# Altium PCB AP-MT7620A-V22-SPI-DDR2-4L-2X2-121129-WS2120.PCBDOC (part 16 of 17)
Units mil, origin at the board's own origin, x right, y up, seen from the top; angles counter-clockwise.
Board outline 7316 x 4279 mil, 4 copper layers (Top, Inner Layer 2, Inner Layer 3, Bottom), stack 35.4 mil thick; 640 components, 473 nets, 2041 pads, 2358 vias.
Unrouted connection lines stored in the file: 11.
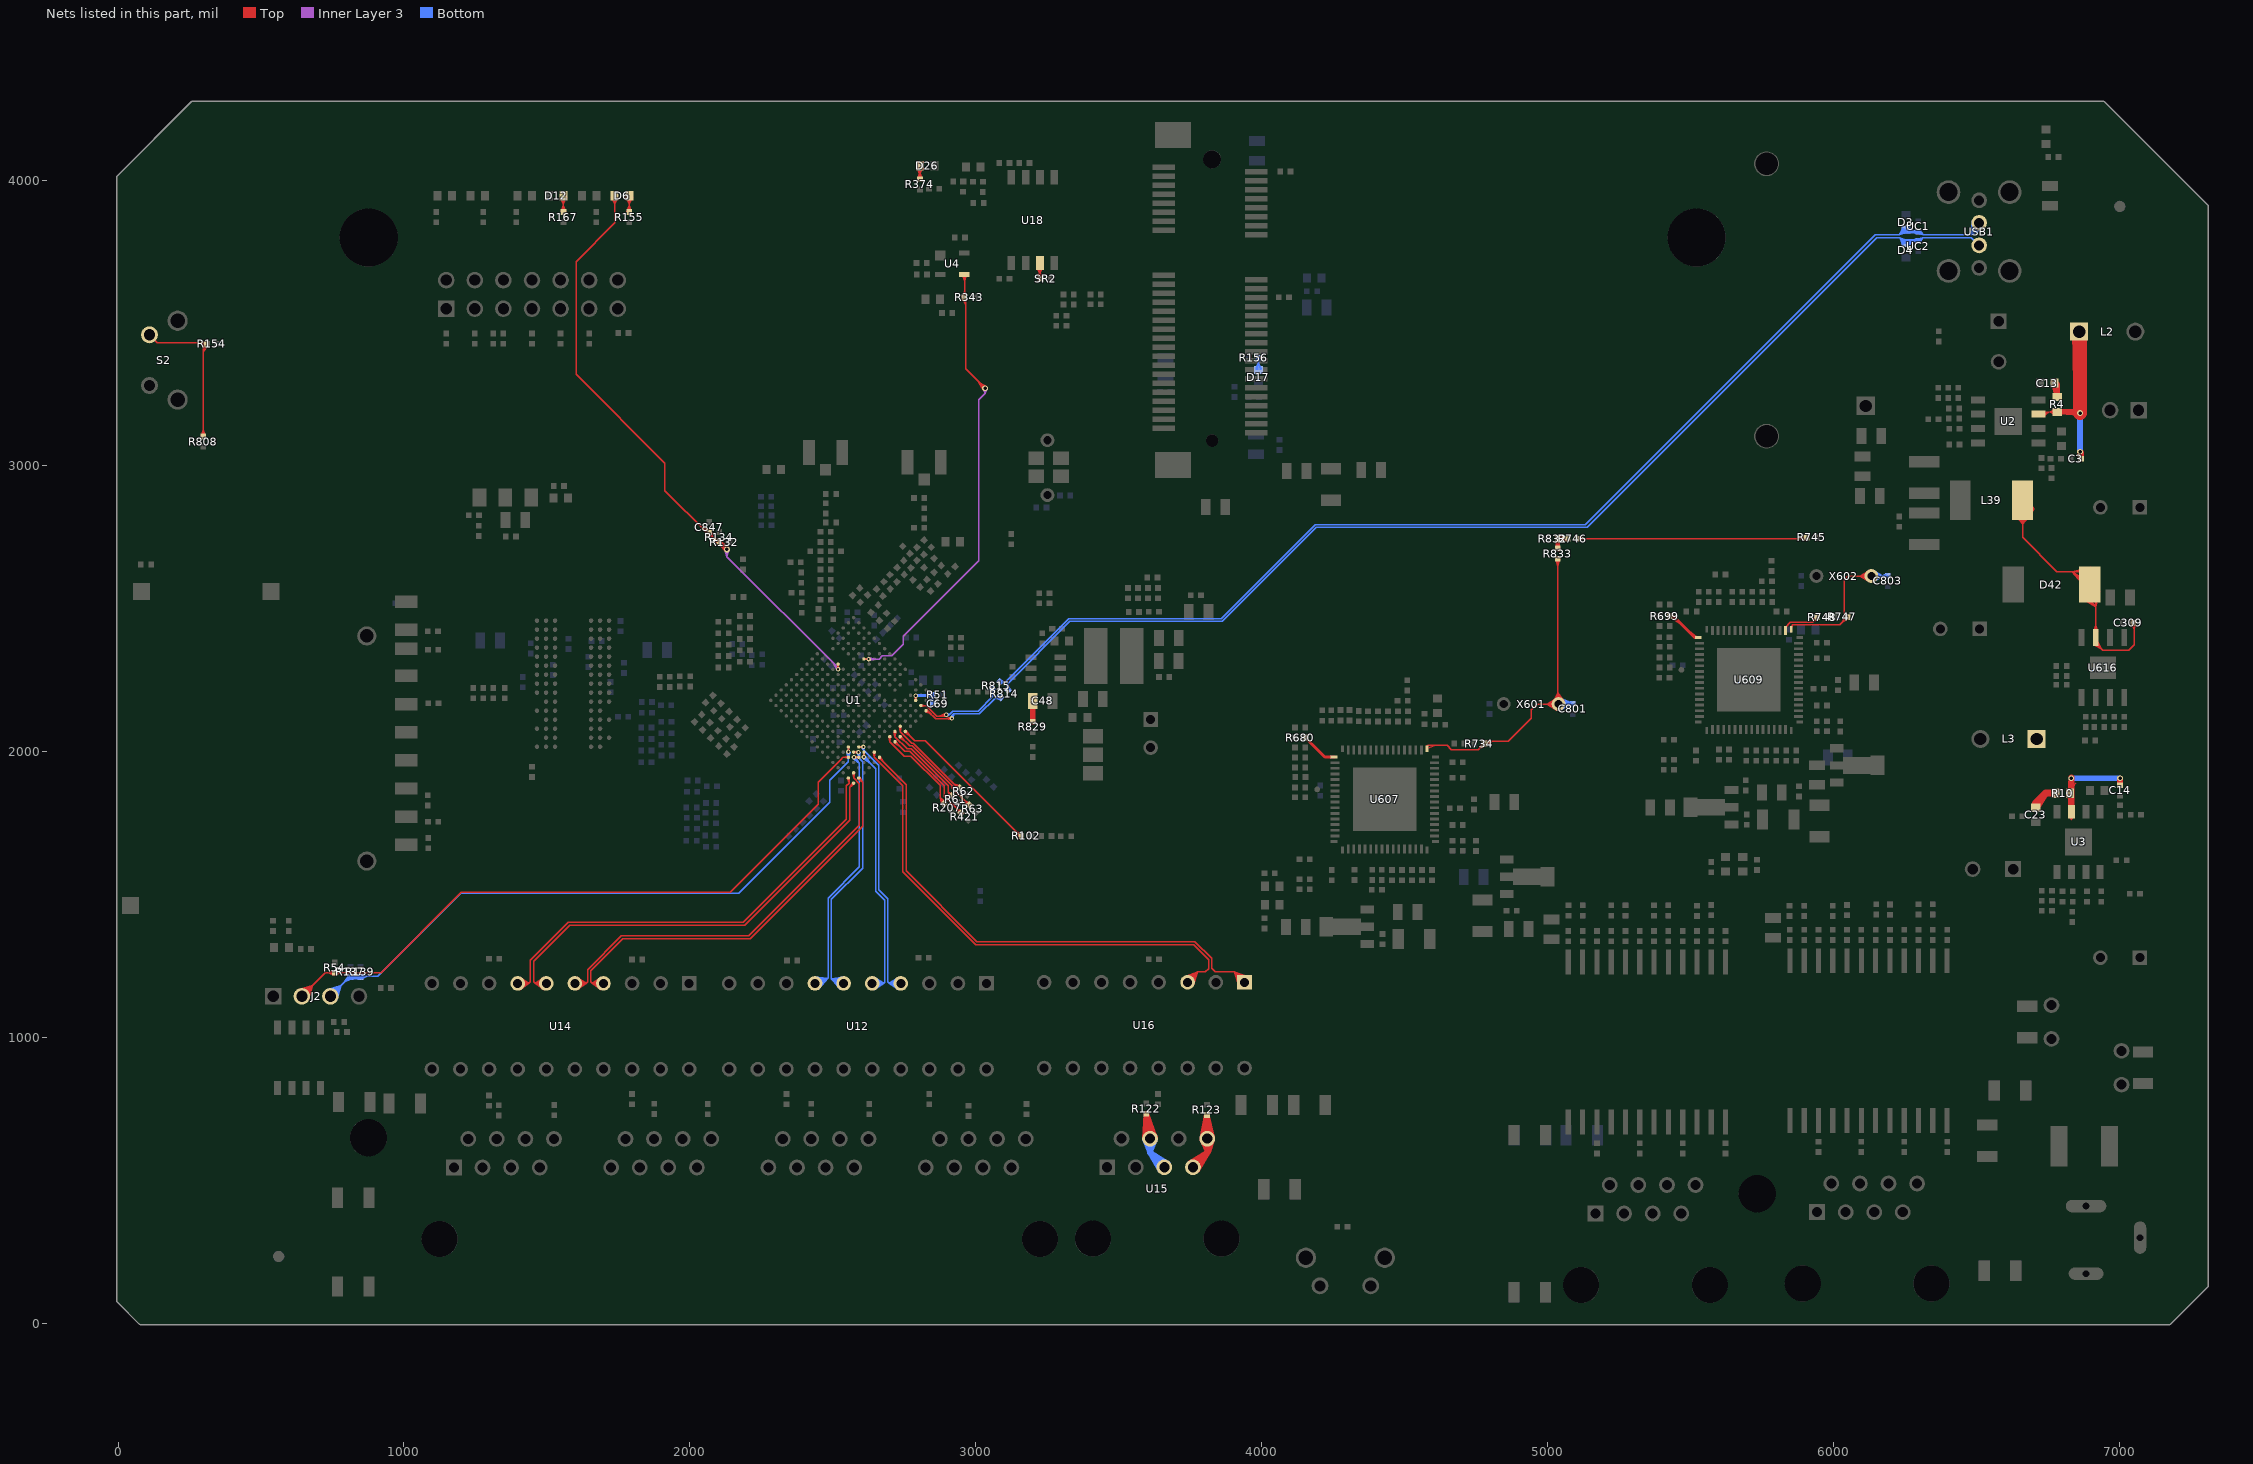
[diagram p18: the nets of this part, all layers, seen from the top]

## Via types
v1: diameter 20, hole 12, Top to Bottom, 2117 vias
v2: diameter 16, hole 8, Top to Bottom, 241 vias

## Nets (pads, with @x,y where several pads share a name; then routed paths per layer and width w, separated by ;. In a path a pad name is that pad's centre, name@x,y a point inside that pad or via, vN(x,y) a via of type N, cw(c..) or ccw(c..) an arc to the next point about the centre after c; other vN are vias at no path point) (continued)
SW1_5-POWER0: C14.2 L3.1 R10.1 U3.3 | length 1273.6
  Top w4: R10.1@6819.19,1864.46 6843.69,1885.69 ; R10.1@6822.03,1861.57 6843.69,1885.69 ; U3.3@6823.33,1775.25 6833,1762.5 ; R10.1@6825.17,1859.08 6843.69,1885.69 ; U3.3@6826.91,1777.3 6833,1762.5 ; R10.1@6828.59,1855 6828.59,1870.59 6850.5,1892.5 ; R10.1@6828.59,1857 6843.69,1885.69 ; U3.3@6830.8,1778.35 6833,1762.5 ; R10.1@6832.24,1855.36 6843.69,1885.69 ; U3.3@6833,1778.5 6833,1762.5 ; U3.3@6833,1789.33 6833,1762.5 ; U3.3@6835.2,1778.35 6833,1762.5 ; R10.1@6836.08,1854.18 6843.69,1885.69 ; U3.3@6839.09,1777.3 6833,1762.5 ; R10.1@6840.06,1853.47 6843.69,1885.69 ; U3.3@6842.67,1775.25 6833,1762.5
  Top w20: R10.1@6828.59,1855 6833,1850.59 6833,1829 ; 6833,1835.98 v1(6832,1908) ; R10.1@6828.59,1853 6833,1829 ; R10.1@6828.59,1853 6833,1829 ; R10.1@6828.59,1853 6833,1802.72 6833,1829 ; R10.1@6828.59,1853 6833,1829 ; R10.1@6828.59,1853 6833,1829 ; R10.1@6828.59,1853 6833,1789.33 6833,1829 ; v1(6832,1908) v1@6833,1911 ; v1(6832,1908) 6828.59,1857 v1@6833,1911 ; 6833,1829 v1@6833,1911 ; C14.2@7003,1883 v1(7003,1908) C14.2@7003,1883
  Bottom w20: v1(6832,1908) v1(7003,1908) 6931,1908
SW2_5-POWER0: C3.2 L2.1 R4.1 U2.3 | length 1467.3
  Top w4: U2.3@6717.61,3181 6717.61,3187.02 6720,3189.41 R4.1@6783,3189.41 ; U2.3@6728.39,3191.12 6754.55,3189.41 ; U2.3@6728.44,3187.07 6754.55,3189.41 ; U2.3@6729.1,3183.12 6754.55,3189.41 ; U2.3@6729.72,3181 6754.55,3189.41 ; U2.3@6730.51,3178.94 6754.55,3189.41 ; U2.3@6732.39,3175.4 6754.55,3189.41 ; U2.3@6734.81,3172.16 6754.55,3189.41 ; R4.1@6778.23,3177.73 6755,3189.41 ; R4.1@6778.23,3201.09 6755,3189.41 ; R4.1@6779.77,3181.5 6755,3189.41 ; R4.1@6779.77,3197.31 6755,3189.41 ; R4.1@6780.69,3185.42 6755,3189.41 ; R4.1@6780.69,3193.4 6755,3189.41 ; R4.1@6781,3189.41 6755,3189.41
  Top w4.5: R4.1@6782,3188.41 R4.1@6783,3189.41
  Top w20: R4.1@6783,3189.41 v1@6858.59,3189.41 ; R4.1@6785,3189.41 v1@6858.59,3189.41 ; v1@6858.59,3189.41 v1(6863,3185) ; v1(6863,3185) 6790.13,3189.41 v1(6863,3185) ; v1(6863,3050) 6866,3047 C3.2@6866,3025 v1(6863,3050)
  Top w50: v1(6863,3185) 6863,3466.57 L2.1@6859.57,3470 6863,3288.34
  Bottom w20: v1(6863,3050) v1(6863,3185) 6863,3113
SW11_5-POWER0: C309.2 D42.2 L39.1 U616.3 | length 3113.5
  Top w4: D42.2@6897.06,2585 D42.2@6897.06,2630
  Top w4.5: L39.1@6630.15,2835.83 6662.25,2797.6 ; L39.1@6633.92,2838.7 6662.25,2797.6 ; L39.1@6637.9,2841.17 6662.25,2797.6 ; L39.1@6642.03,2843.24 6662.25,2797.6 ; L39.1@6646.3,2844.9 6662.25,2797.6 ; L39.1@6662.25,2880 6662.25,2750 6782.25,2630 6897.06,2630 6917.06,2630 6917.06,2570 6918,2569.06 U616.3@6918,2399.33 6923,2394.33 6923,2375 6943,2355 7033,2355 7053,2375 7053,2448 C309.2@7049,2452 7053,2427.56 ; L39.1@6678.21,2844.9 6662.25,2797.6 ; L39.1@6682.47,2843.24 6662.25,2797.6 ; L39.1@6686.61,2841.17 6662.25,2797.6 ; L39.1@6690.58,2838.7 6662.25,2797.6 ; L39.1@6694.36,2835.83 6662.25,2797.6 ; D42.2@6869.64,2537.58 6918,2506.88 ; D42.2@6872.32,2541.44 6918,2506.88 ; D42.2@6875.27,2545.03 6918,2506.88 ; D42.2@6877.22,2580.31 6835.19,2630 ; D42.2@6878.47,2548.34 6918,2506.88 ; D42.2@6880.66,2583.44 6835.19,2630 ; D42.2@6881.9,2551.36 6918,2506.88 ; D42.2@6883.84,2586.78 6835.19,2630 ; D42.2@6886.76,2590.31 6835.19,2630 ; D42.2@6889.41,2594.01 6835.19,2630 ; D42.2@6898.44,2645.32 6835.19,2630 ; D42.2@6899.37,2640.76 6835.19,2630 ; D42.2@6899.97,2636.19 6835.19,2630 ; D42.2@6900.2,2627.06 6835.19,2630 ; D42.2@6900.25,2631.62 6835.19,2630 ; U616.3@6910.32,2420.11 6918,2442.36 ; U616.3@6913.31,2373.62 6938.38,2359.62 ; D42.2@6914.18,2564.04 6918,2506.88 ; U616.3@6914.72,2419.05 6918,2442.36 ; U616.3@6915.82,2377.38 6938.38,2359.62 ; U616.3@6918,2379.84 6938.38,2359.62 ; U616.3@6918,2418.82 6918,2442.36 ; D42.2@6918.74,2564.16 6918,2506.88 ; U616.3@6920.45,2382.04 6938.38,2359.62 ; U616.3@6921.28,2419.05 6918,2442.36 ; D42.2@6923.34,2563.91 6918,2506.88 ; U616.3@6924.19,2384.58 6938.38,2359.62 ; U616.3@6925.68,2420.11 6918,2442.36 ; D42.2@6927.95,2563.29 6918,2506.88 ; D42.2@6932.54,2562.29 6918,2506.88 ; C309.2@7041.64,2449.57 7053,2427.56 ; C309.2@7045.83,2451.27 7053,2427.56 ; C309.2@7052.24,2452.31 7053,2427.56 ; C309.2@7056.75,2452.04 7053,2427.56
  Top w20: L39.1@6662.25,2880 L39.1@6693,2849.25
SW_C2_5-POWER0: C13.1 R4.2 | length 104.2
  Top w20: C13.1@6773.59,3288 R4.2@6783,3240.59 6783,3285 6778.59,3285 C13.1@6773.59,3290
SW_C_5-POWER0: C23.1 R10.2 | length 209.2
  Top w25: C23.1@6710,1805.59 6742.5,1855.5 ; 6708,1821 6742.5,1855.5 ; 6708,1821 C23.1@6708,1805.59 6708,1821 ; 6742.5,1855.5 6776.91,1855.5 R10.2@6777.41,1855 6742.5,1855.5
TXCLK_1-CPU-RT0: R102.2 U1.G17 | length 709.6
  Top w5: U1.G17@2751.76,2068.82 2768.79,2056.71 ; U1.G17@2756.54,2073.64 2768.79,2056.71 ; R102.2@3153.41,1701 3136.71,1725.29 ; R102.2@3163.15,1712.25 3136.71,1725.29 ; 2768.79,2056.71 U1.G17@2753.95,2071.43 2754.07,2071.43 2786.5,2039 2823,2039 3152,1710 3156,1710 3160,1706 R102.2@3159,1706 3136.71,1725.29
TXD0_1-CPU-RT0: R63.2 U1.H17 | length 523
  Top w4.5: U1.H17@2733.53,2050.52 2749.58,2039.61 ; U1.H17@2738.67,2055.66 2749.58,2039.61 ; R63.2@2970.68,1809.94 2960.37,1831.06 ; R63.2@2974.54,1812.31 2960.37,1831.06 ; R63.2@2976.99,1814.45 2960.37,1831.06 ; R63.2@2977.7,1813.74 2978.4,1813.03 2918,1873.43 2918,1880.62 2778.04,2020.57 2768.62,2020.57 U1.H17@2735.86,2053.33 2749.58,2039.61 ; R63.2@2979.12,1816.9 2960.37,1831.06 ; R63.2@2981.49,1820.75 2960.37,1831.06
TXD1_1-CPU-RT0: R61.2 U1.H16 | length 463.6
  Top w4.5: U1.H16@2714.13,2071.06 2717.76,2053.34 ; U1.H16@2721.4,2071.06 2717.76,2053.34 ; R61.2@2910.36,1842.08 2904.08,1859.08 ; R61.2@2914.39,1844.18 2904.08,1859.08 ; R61.2@2916.89,1846.27 2904.08,1859.08 ; R61.2@2917.59,1845.56 2918.3,1844.85 2904.08,1859.08 ; R61.2@2918.97,1848.76 2904.08,1859.08 ; R61.2@2921.07,1852.79 2904.08,1859.08 ; 2717.76,2053.34 U1.H16@2717.76,2071.43 2717.76,2053.34 ; 2717.76,2053.34 2760.29,2010.81 2774.19,2010.81 2904.08,1880.92 2904.08,1859.08
TXD2_1-CPU-RT0: R421.2 U1.J17 | length 534.5
  Top w4.5: U1.J17@2715.48,2032.38 2731.74,2021.76 ; U1.J17@2720.54,2037.62 2731.74,2021.76 ; R421.2@2942.28,1781.83 2932.51,1803.24 ; R421.2@2946.2,1784.09 2932.51,1803.24 ; R421.2@2948.7,1786.16 2932.51,1803.24 ; R421.2@2949.41,1785.45 2950.12,1784.75 2945.75,1789.12 2945.75,1790 2890.75,1845 2890.75,1880.75 2770.25,2001.26 2752.24,2001.26 2718.26,2035.24 U1.J17@2717.76,2035.24 2731.74,2021.76 ; R421.2@2950.9,1788.56 2932.51,1803.24 ; R421.2@2953.37,1792.35 2932.51,1803.24
TXD3_1-CPU-RT0: R207.2 U1.J16 | length 514
  Top w4.5: U1.J16@2696.04,2052.88 2700.13,2034.87 ; U1.J16@2703.31,2053.06 2700.13,2034.87 ; R207.2@2881.41,1815.1 2875.86,1839.39 ; R207.2@2885.71,1816.5 2875.86,1839.39 ; R207.2@2888.6,1817.98 2875.86,1839.39 ; R207.2@2890.01,1816.57 2889.33,1817.25 2888,1817.25 2893,1822.25 2875.25,1840 2875.25,1882.8 2773.05,1985 2750,1985 2700.13,2034.87 ; R207.2@2891.28,1819.82 2875.86,1839.39 ; R207.2@2894.56,1822.93 2875.86,1839.39 ; 2700.13,2034.87 2700.13,2052.87 U1.J16@2699.67,2053.33 2700.13,2034.87
TXDELAY_IP1001-2_1-CPU-RT0: R699.1 U609.49 | length 235
  Top w10: 5465.42,2449.58 R699.1@5428,2475 ; 5493.63,2421.37 U609.49@5520.93,2399.69 ; U609.49@5527.82,2399.69 5527.51,2400 5515,2400 ; R699.1@5428,2475 5440,2475 ; R699.1@5428,2475 5440,2475 ; 5440,2475 5515,2400 ; 5515,2400 U609.49@5520.93,2399.69 ; 5515,2400 U609.49@5520.93,2399.69
TXDELAY_IP1001_1-CPU-RT0: R680.1 U607.49 | length 154.7
  Top w10: R680.1@4153,2050 4221.31,1981.69 ; U607.49@4246.93,1981.69 4221.31,1981.69 ; U607.49@4253.82,1981.69 4221.31,1981.69
TXEN_1-CPU-RT0: R62.2 U1.G16 | length 497.5
  Top w4.5: U1.G16@2732.23,2089.04 2736.53,2070.77 ; U1.G16@2739.51,2089.3 2736.53,2070.77 ; R62.2@2940.03,1868.75 2923.46,1888.6 ; R62.2@2943.24,1871.94 2923.46,1888.6 ; R62.2@2945.17,1874.55 2923.46,1888.6 ; R62.2@2945.88,1873.84 2946.58,1873.14 2938.93,1873.14 2781.87,2030.2 2777.1,2030.2 2736.53,2070.77 ; R62.2@2946.76,1877.38 2923.46,1888.6 ; R62.2@2948.36,1881.61 2923.46,1888.6 ; 2736.53,2070.77 2736.53,2088.85 U1.G16@2735.86,2089.52 2736.53,2070.77
TXOM0: U1.U17 U14.6 | length 1993.7
  Top w5: U14.6@1491.16,1167.94 1459,1190 ; U14.6@1491.16,1212.06 1459,1190 ; U14.6@1493.8,1172.4 1459,1190 ; U14.6@1493.8,1207.6 1459,1190 ; U14.6@1495.8,1177.1 1459,1190 ; U14.6@1495.8,1202.9 1459,1190 ; U14.6@1497.16,1181.95 1459,1190 ; U14.6@1497.16,1198.05 1459,1190 ; U14.6@1497.88,1186.91 1459,1190 ; U14.6@1497.88,1193.09 1459,1190 ; U14.6@1498,1190 1459,1190 ; U1.U17@2570.39,1892.67 2559,1876.48 ; U1.U17@2573,1890.48 2559,1876.48 ; U1.U17@2575.19,1887.87 2559,1876.48 ; 1459,1190 1453.5,1195.5 1453.5,1267.23 1579.27,1393 2191.56,1393 2559,1760.44 2559,1809.82 2559,1876.48
TXOM1: U1.T17 U14.4 | length 1870.1
  Top w5: U14.4@1691.16,1167.94 1659,1190 ; U14.4@1691.16,1212.06 1659,1190 ; U14.4@1693.8,1172.4 1659,1190 ; U14.4@1693.8,1207.6 1659,1190 ; U14.4@1695.8,1177.1 1659,1190 ; U14.4@1695.8,1202.9 1659,1190 ; U14.4@1697.16,1181.95 1659,1190 ; U14.4@1697.16,1198.05 1659,1190 ; U14.4@1697.88,1186.91 1659,1190 ; U14.4@1697.88,1193.09 1659,1190 ; U14.4@1698,1190 1659,1190 ; U1.T17@2588.8,1906.06 2604.5,1894 ; U1.T17@2593.79,1910.65 2604.5,1894 ; 1659,1190 1653.5,1195.5 1653.5,1233.83 1765.67,1346 2211.06,1346 2604.5,1739.44 2604.5,1894 ; 2604.5,1894 2590.51,1907.99 U1.T17@2591.1,1908.57 2604.5,1894
TXOM2: U1.P15 U12.7 | length 1479.8
  Top w5: U1.P15@2591.05,1981 U1.P15@2591.1,1980.95
  Top w8: U1.P15@2591.05,1981 v2(2574.5,1981) U1.P15@2591.1,1980.95
  Bottom w5: U12.7@2434.44,1207.74 2482.69,1208.19 ; U12.7@2434.67,1212.85 2482.69,1208.19 ; U12.7@2434.76,1202.68 2482.69,1208.19 ; U12.7@2435.59,1197.72 2482.69,1208.19 ; U12.7@2436.93,1192.9 2482.69,1208.19 ; U12.7@2438,1190 2464.5,1190 2483.5,1209 2483.5,1488.12 2593.5,1598.12 2593.5,1959.5 2577.5,1975.5 2577.5,1978 v2(2574.5,1981) 2593.32,1959.68 ; U12.7@2439.26,1187.18 2482.69,1208.19 ; U12.7@2441.67,1182.79 2482.69,1208.19 ; U12.7@2444.53,1178.66 2482.69,1208.19 ; U12.7@2447.84,1174.82 2482.69,1208.19 ; U12.7@2451.57,1171.32 2482.69,1208.19 ; v2@2570.75,1976.98 2593.32,1959.68 ; v2@2578.96,1984.22 2593.32,1959.68
TXOM3: U1.N14 U12.4 | length 1402.4
  Top w8: U1.N14@2591.1,2017.14 2607.44,2017.14 U1.N14@2591.1,2017.14 ; U1.N14@2591.1,2017.14 v2(2607.5,2017.2) U1.N14@2591.1,2017.14
  Top w10: v2@2607.44,2017.14 v2(2607.5,2017.2)
  Bottom w5: v2@2602.18,2015.79 2607.5,2006.5 ; v2@2612.82,2015.79 2607.5,2006.5 ; U12.4@2731.34,1167.89 2698,1190 ; U12.4@2731.34,1212.11 2698,1190 ; U12.4@2733.91,1172.38 2698,1190 ; U12.4@2733.91,1207.62 2698,1190 ; U12.4@2735.86,1177.09 2698,1190 ; U12.4@2735.86,1202.91 2698,1190 ; U12.4@2737.18,1181.95 2698,1190 ; U12.4@2737.18,1198.05 2698,1190 ; U12.4@2737.88,1186.91 2698,1190 ; U12.4@2737.88,1193.09 2698,1190 ; U12.4@2738,1190 2698,1190 ; 2607.5,2006.5 v2(2607.5,2017.2) 2607.5,2006.5 ; 2607.5,2006.5 2661,1953 2661,1517 2692.5,1485.5 2692.5,1195.5 2698,1190
TXOM4: U1.M17 U16.1 | length 2374.1
  Top w5: U1.M17@2661.07,1978.55 2677.26,1964.74 ; U1.M17@2666.24,1982.94 2677.26,1964.74 ; U16.1@3920.79,1181.8 3904.39,1230 ; U16.1@3925.53,1183.68 3904.39,1230 ; U16.1@3930.02,1186.01 3904.39,1230 ; U16.1@3934.24,1188.75 3904.39,1230 ; U16.1@3938.14,1191.88 3904.39,1230 ; U16.1@3940.39,1194 3904.39,1230 ; U16.1@3942.51,1196.25 3904.39,1230 ; U16.1@3945.64,1200.16 3904.39,1230 ; U16.1@3948.38,1204.37 3904.39,1230 ; U16.1@3950.71,1208.86 3904.39,1230 ; U16.1@3952.59,1213.6 3904.39,1230 ; 2677.26,1964.74 U1.M17@2663.48,1980.95 2663.48,1978.52 2756.5,1885.5 2756.5,1584.28 3004.28,1336.5 3766.72,1336.5 3825.5,1277.72 3825.5,1243 3838.5,1230 3904.39,1230
TXOP0: U1.U16 U14.7 | length 2026.4
  Top w5: U14.7@1398,1190 1437,1190 ; U14.7@1398.12,1186.91 1437,1190 ; U14.7@1398.12,1193.09 1437,1190 ; U14.7@1398.84,1181.95 1437,1190 ; U14.7@1398.84,1198.05 1437,1190 ; U14.7@1400.2,1177.1 1437,1190 ; U14.7@1400.2,1202.9 1437,1190 ; U14.7@1402.2,1172.4 1437,1190 ; U14.7@1402.2,1207.6 1437,1190 ; U14.7@1404.84,1167.94 1437,1190 ; U14.7@1404.84,1212.06 1437,1190 ; U1.U16@2551.58,1907.84 2557.2,1890.3 ; U1.U16@2558.31,1908.68 2557.2,1890.3 ; 1437,1190 1442.5,1195.5 1442.5,1271.79 1574.71,1404 2187,1404 2548,1765 2548,1881.1 2557.2,1890.3 ; 2557.2,1890.3 2557.2,1906.28 U1.U16@2554.9,1908.57 2557.2,1890.3
TXOP1: U1.T16 U14.5 | length 1885.5
  Top w5: U14.5@1598,1190 1637,1190 ; U14.5@1598.12,1186.91 1637,1190 ; U14.5@1598.12,1193.09 1637,1190 ; U14.5@1598.84,1181.95 1637,1190 ; U14.5@1598.84,1198.05 1637,1190 ; U14.5@1600.2,1177.1 1637,1190 ; U14.5@1600.2,1202.9 1637,1190 ; U14.5@1602.2,1172.4 1637,1190 ; U14.5@1602.2,1207.6 1637,1190 ; U14.5@1604.84,1167.94 1637,1190 ; U14.5@1604.84,1212.06 1637,1190 ; U1.T16@2569.61,1926.35 2573,1908.6 ; U1.T16@2576.39,1926.35 2573,1908.6 ; 1637,1190 1642.5,1195.5 1642.5,1238.39 1761.11,1357 2206.5,1357 2593.5,1744 2593.5,1888.1 2573,1908.6 ; 2573,1908.6 U1.T16@2573,1926.67 2573,1908.6
TXOP2: U1.P14 U12.6 | length 2035.5
  Top w8: U1.P14@2573,1999.05 v2(2590,1999) U1.P14@2573,1999.05 ; U1.P14@2573,1999.05 v2(2590,1999) U1.P14@2573,1999.05
  Top w10: v2(2590,1999) v2(2590,1999)
  Bottom w5: U12.6@2524.68,1171.14 2495.87,1205.63 ; U12.6@2528.42,1174.65 2495.87,1205.63 ; U12.6@2531.71,1178.52 2495.87,1205.63 ; U12.6@2534.51,1182.7 2495.87,1205.63 ; U12.6@2536.83,1187.14 2495.87,1205.63 ; U12.6@2538,1190 2533,1190 2531.5,1191.5 2510,1191.5 ; U12.6@2538.97,1192.93 2495.87,1205.63 ; U12.6@2540.12,1197.81 2495.87,1205.63 ; U12.6@2540.2,1212.99 2495.87,1205.63 ; U12.6@2540.72,1202.81 2495.87,1205.63 ; U12.6@2540.75,1207.88 2495.87,1205.63 ; v2@2584.64,1997.77 2592,1978 ; v2@2595.5,1998.8 2592,1978 ; 2510,1191.5 2494.5,1207 2494.5,1483.56 2604.5,1593.56 2604.5,1965.5 2592,1978 ; 2510,1191.5 2527.38,1169.5 2510,1191.5 ; 2510,1191.5 2529.63,1211.52 2510,1191.5 ; 2510,1191.5 2531.26,1173.21 2510,1191.5 ; 2510,1191.5 2533.09,1207.41 2510,1191.5 ; 2510,1191.5 2534.27,1177.45 2510,1191.5 ; 2510,1191.5 2535.63,1202.87 2510,1191.5 ; 2510,1191.5 2536.41,1182.07 2510,1191.5 ; 2510,1191.5 2537.26,1198.06 2510,1191.5 ; 2510,1191.5 2537.66,1186.93 2510,1191.5 ; 2510,1191.5 2538,1193.09 2510,1191.5 ; 2592,1978 2592,1997 v2(2590,1999) 2592,1978
TXOP3: U1.N15 U12.5 | length 1390.2
  Top w8: U1.N15@2609.19,1999.05 2609.19,1981.99 U1.N15@2609.19,1999.05 ; U1.N15@2609.19,1999.05 v2(2609.1,1981.9) U1.N15@2609.19,1999.05
  Top w10: v2(2609.1,1981.9) v2@2609.19,1981.99
  Bottom w5: v2@2605.6,1977.66 2629.72,1961.33 v2@2613.33,1985.41 ; v2(2609.1,1981.9) 2650,1941.1 2650,1512.5 2650,1512.44 2681.5,1480.94 2681.5,1193.5 2678,1190 ; U12.5@2638,1190 2678,1190 ; U12.5@2638.12,1186.91 2678,1190 ; U12.5@2638.12,1193.09 2678,1190 ; U12.5@2638.82,1181.95 2678,1190 ; U12.5@2638.82,1198.05 2678,1190 ; U12.5@2640.14,1177.09 2678,1190 ; U12.5@2640.14,1202.91 2678,1190 ; U12.5@2642.09,1172.38 2678,1190 ; U12.5@2642.09,1207.62 2678,1190 ; U12.5@2644.66,1167.89 2678,1190 ; U12.5@2644.66,1212.11 2678,1190
TXOP4: U1.M16 U16.3 | length 2344.6
  Top w4.5: U1.M16@2641.74,1998.68 2645.38,1981 ; U1.M16@2649.02,1998.68 2645.38,1981 ; 2668,1958.38 2645.38,1981 ; 2645.38,1981 U1.M16@2645.38,1999.05 2645.38,1981
  Top w5: 2668,1958.38 2745.5,1880.88 2745.5,1579.72 2999.72,1325.5 3762.16,1325.5 3814.5,1273.16 3814.5,1241.5 3803,1230 3777.3,1230 ; U16.3@3729.1,1213.6 3777.3,1230 ; U16.3@3730.98,1208.86 3777.3,1230 ; U16.3@3733.31,1204.37 3777.3,1230 ; U16.3@3736.05,1200.16 3777.3,1230 ; U16.3@3739.18,1196.25 3777.3,1230 ; U16.3@3741.3,1194 3777.3,1230 ; U16.3@3743.55,1191.88 3777.3,1230 ; U16.3@3747.46,1188.75 3777.3,1230 ; U16.3@3751.67,1186.01 3777.3,1230 ; U16.3@3756.16,1183.68 3777.3,1230 ; U16.3@3760.9,1181.8 3777.3,1230
UART_RX_1-CPU-RT0: J2.2 R54.1 U1.R14 | length 3226.2
  Top w4.5: J2.2@629.3,1167.98 681.55,1183.55 ; J2.2@630.81,1163.61 681.55,1183.55 ; J2.2@632.66,1159.43 681.55,1183.55 ; J2.2@634.84,1155.44 681.55,1183.55 ; J2.2@637.33,1151.66 681.55,1183.55 ; J2.2@643,1145 725,1227 ; J2.2@649.66,1139.33 681.55,1183.55 ; J2.2@653.44,1136.84 681.55,1183.55 ; J2.2@657.43,1134.66 681.55,1183.55 ; J2.2@661.61,1132.81 681.55,1183.55 ; J2.2@665.98,1131.3 681.55,1183.55 ; R54.1@756.4,1219.42 734.48,1228 ; R54.1@756.72,1219.36 734.5,1227 ; R54.1@756.72,1234.64 734.5,1227 ; R54.1@757.05,1234.69 734.48,1228 ; R54.1@757.64,1223.77 734.48,1228 ; R54.1@757.78,1223.76 734.5,1227 ; R54.1@757.78,1230.24 734.5,1227 ; R54.1@757.91,1230.25 734.48,1228 ; R54.1@758.22,1223.76 781.5,1227 ; R54.1@758.22,1230.24 781.5,1227 ; R54.1@759.28,1219.36 781.5,1227 ; R54.1@759.28,1234.64 781.5,1227 ; U1.R14@2554.54,1977.32 2536.5,1980.96 ; U1.R14@2554.54,1984.59 2536.5,1980.96 ; U1.R14@2554.91,1980.96 2536.5,1980.96 ; 725,1227 726,1228 758,1228 R54.1@758,1227 734.48,1228 ; 725,1227 920,1227 1201,1508 2142,1508 2450,1816 2450,1894.3 2532.34,1976.64 2532.34,1976.8 2536.5,1980.96
UART_TX: J2.3 R137.2 R139.2 U1.P13 | length 4096.1
  Top w8: U1.P13@2554.9,2017.14 2554.9,1999.9 U1.P13@2554.9,2017.14 ; U1.P13@2554.9,2017.14 v2(2555,2000) U1.P13@2554.9,2017.14
  Top w10: v2@2554.9,1999.9 v2(2555,2000)
  Bottom w4.5: J2.3@729.3,1167.98 781.55,1183.55 ; J2.3@730.81,1163.61 781.55,1183.55 ; J2.3@732.66,1159.43 781.55,1183.55 ; J2.3@734.84,1155.44 781.55,1183.55 ; J2.3@737.33,1151.66 781.55,1183.55 ; J2.3@743,1145 813,1215 R137.2@818,1215 ; J2.3@749.66,1139.33 781.55,1183.55 ; J2.3@753.44,1136.84 781.55,1183.55 ; J2.3@757.43,1134.66 781.55,1183.55 ; J2.3@761.61,1132.81 781.55,1183.55 ; J2.3@765.98,1131.3 781.55,1183.55 ; R137.2@807.18,1217.12 792.1,1194.1 ; R137.2@810.74,1214.34 792.1,1194.1 ; R137.2@812.38,1219.73 R139.2@839.02,1217.98 ; R137.2@812.47,1215.21 R139.2@839.02,1217.98 ; R137.2@812.62,1204.26 R139.2@841.33,1206.74 ; R137.2@812.59,1208.78 R139.2@841.33,1206.74 ; R137.2@813.01,1208.75 R139.2@841.34,1210.43 ; R137.2@813.08,1215.25 R139.2@840.94,1212.89 ; R137.2@813.2,1219.75 R139.2@840.25,1215.16 ; R137.2@813.29,1208.76 R139.2@840.94,1212.89 ; R137.2@813.28,1219.74 836.94,1215 ; R137.2@813.37,1215.23 R139.2@841.34,1210.43 ; R137.2@813.57,1208.8 R139.2@840.25,1215.16 ; R137.2@813.62,1208.81 836.94,1215 ; R137.2@813.63,1204.28 R139.2@841.34,1210.43 ; R137.2@813.77,1215.16 R139.2@841.33,1206.74 ; R137.2@813.83,1219.71 R139.2@840.94,1212.89 ; R137.2@813.92,1208.88 R139.2@839.02,1217.98 ; R137.2@814.32,1204.36 R139.2@840.94,1212.89 ; R137.2@814.48,1219.61 R139.2@841.34,1210.43 ; R137.2@814.97,1204.5 R139.2@840.25,1215.16 ; R137.2@814.96,1209.41 792.1,1194.1 ; R137.2@815.19,1204.56 836.94,1215 ; R137.2@815.43,1219.36 R139.2@841.33,1206.74 ; R137.2@815.81,1204.78 R139.2@839.02,1217.98 ; R137.2@817.16,1205.46 792.1,1194.1 ; R139.2@845.79,1204.57 824.3,1215 ; R139.2@847.37,1208.81 824.3,1215 ; R139.2@847.71,1219.74 824.3,1215 ; R139.2@847.81,1215.24 871.81,1215 ; R139.2@848.19,1215.24 824.3,1215 ; R139.2@848.29,1219.74 871.81,1215 ; R139.2@848.62,1208.81 871.81,1215 ; R139.2@850.2,1204.57 871.81,1215 ; v2@2549.29,1999.3 2555,1976.5 v2@2560.71,1999.3 ; v2(2555,2000) 2555,1965 2490,1900 2490,1824 2171,1505 1198,1505 908,1215 R139.2@848,1215 ; 792.1,1194.1 R137.2@813,1212 ; R137.2@813,1212 813,1213 816,1213 R137.2@818,1215 ; R137.2@813,1212 836.94,1215 ; R137.2@813,1212 R139.2@841.33,1206.74 ; R137.2@813,1212 R139.2@839.02,1217.98 ; R137.2@813,1212 R139.2@841.34,1210.43 ; R137.2@813,1212 R139.2@840.25,1215.16 ; R137.2@813,1212 R139.2@840.94,1212.89 ; R137.2@818,1215 R139.2@848,1215 ; 824.3,1215 R139.2@848,1212 ; 836.94,1215 812.81,1215.25 R139.2@840.25,1215.16 ; R139.2@848,1212 R139.2@848,1215 ; R139.2@848,1212 871.81,1215
UPHY0_PADM_0_1-CPU-RT0: D3.2 R815.1 UC1.1 USB1.2 | length 5309.6
  Bottom w4.5: D3.2@6242.77,3833.69 6230,3808 ; D3.2@6246.68,3831.34 6230,3808 ; D3.2@6250.14,3828.43 6230,3808 ; D3.2@6252,3826.41 6230,3808 ; D3.2@6253.66,3824.22 6230,3808 ; D3.2@6253.88,3814.85 6285.69,3815 ; D3.2@6254,3826.41 6255.59,3824.82 D3.2@6255.59,3820.41 ; D3.2@6254.19,3819.39 6285.69,3815 ; D3.2@6255.13,3823.8 6285.69,3815 ; D3.2@6255.91,3820.31 6230,3808 ; D3.2@6256,3826.41 6285.69,3815 ; D3.2@6257.1,3828.93 6285.69,3815 ; D3.2@6257.54,3816.04 6230,3808 ; D3.2@6259.35,3832.84 6285.69,3815 ; D3.2@6262.17,3836.41 6285.69,3815 ; UC1.1@6294.3,3827.27 6272.41,3815 ; UC1.1@6296.15,3823.14 6272.41,3815 ; UC1.1@6297.35,3812.26 6272.41,3815 ; UC1.1@6297.44,3816.78 6272.41,3815 ; UC1.1@6301,3821 UC1.1@6297,3825 ; 6230,3808 6255.59,3833.59 D3.2@6255.59,3820.41 ; D3.2@6255.59,3820.41 6261,3815 6292.41,3815 UC1.1@6297,3825 ; 6272.41,3815 UC1.1@6297,3820 UC1.1@6297,3825
  Bottom w5: R815.1@3085.94,2237.33 3103.66,2244.02 ; R815.1@3086.49,2252.02 3103.66,2244.02 ; 6230,3808 6146.04,3808 5133.04,2795 4187.53,2795 3858.53,2466 3325.64,2466 3103.66,2244.02 ; UC1.1@6293.85,3813.19 6314,3808 ; UC1.1@6297,3820 6314,3808 ; UC1.1@6301,3821 6314,3808 ; UC1.1@6302.36,3825.25 6314,3808 ; USB1.2@6486.33,3858.49 6482.61,3809.61 ; USB1.2@6491.42,3857.83 6482.61,3809.61 ; USB1.2@6496.37,3856.66 6482.61,3809.61 ; USB1.2@6501.13,3855 6482.61,3809.61 ; USB1.2@6505.66,3852.87 6482.61,3809.61 ; USB1.2@6510,3850.26 6508,3848.26 6508,3835 6481,3808 6314,3808 ; USB1.2@6514.04,3847.22 6482.61,3809.61 ; USB1.2@6517.72,3843.81 6482.61,3809.61 ; USB1.2@6521.05,3840.03 6482.61,3809.61 ; USB1.2@6523.99,3835.88 6482.61,3809.61 ; USB1.2@6526.51,3831.41 6482.61,3809.61 ; 3103.66,2244.02 3084.02,2244.02 R815.1@3084.73,2244.73 3103.66,2244.02
UPHY0_PADM_1-CPU-RT0: R815.2 U1.C16 | length 556.4
  Top w4.5: U1.C16@2808.61,2158.27 2826.33,2161.9 ; U1.C16@2808.61,2165.54 2826.33,2161.9 ; 2836.57,2151.67 2826.33,2161.9 ; 2826.33,2161.9 U1.C16@2808.24,2161.9 2826.33,2161.9
  Top w5: 2836.57,2151.67 2837.74,2150.5 2837.93,2150.5 2863.93,2124.5 2891.5,2124.5 v2(2897,2130) 2870.59,2124.5 ; v2@2895.34,2135.24 2870.59,2124.5 ; v2@2897.57,2124.53 2870.59,2124.5
  Bottom w5: v2(2897,2130) 2907.5,2130 ; v2@2898.44,2124.69 2907.5,2130 ; v2@2898.44,2135.31 2907.5,2130 ; R815.2@3051.89,2217.97 3059.98,2193.62 ; R815.2@3066.72,2218.38 3059.98,2193.62 ; 2907.5,2130 2920,2142.5 2922,2142.5 3008.86,2142.5 3059.98,2193.62 ; 3059.98,2193.62 3059.98,2219.98 R815.2@3059.27,2219.27 3059.98,2193.62
UPHY0_PADP_0_1-CPU-RT0: D4.2 R814.1 UC2.1 USB1.3 | length 4814
  Bottom w4.5: 6230.59,3798.5 6233.09,3798.5 ; D4.2@6242.07,3773.31 6233.09,3798.5 ; D4.2@6246.23,3775.21 6233.09,3798.5 ; D4.2@6249.96,3777.75 6233.09,3798.5 ; D4.2@6253.84,3781.63 6233.09,3798.5 ; D4.2@6253.86,3791.14 6285.29,3791 ; D4.2@6254.17,3786.6 6285.29,3791 ; D4.2@6255.11,3782.19 6285.29,3791 ; D4.2@6256,3779.59 6285.29,3791 ; D4.2@6256.38,3785.36 6233.09,3798.5 ; D4.2@6257.11,3777.07 6285.29,3791 ; D4.2@6258.28,3789.52 6233.09,3798.5 ; D4.2@6259.39,3773.18 6285.29,3791 ; D4.2@6262.24,3769.63 6285.29,3791 ; UC2.1@6293.8,3794.06 6313,3798.5 ; UC2.1@6294.52,3779.66 6273.06,3791 ; UC2.1@6295.33,3789.79 6313,3798.5 ; UC2.1@6296.25,3783.84 6273.06,3791 ; UC2.1@6297.04,3794.75 6273.06,3791 ; UC2.1@6297.32,3790.23 6273.06,3791 ; UC2.1@6299.11,3784.53 6313,3798.5 ; UC2.1@6302.67,3781.72 6313,3798.5 ; 6233.09,3798.5 D4.2@6252,3779.59 ; 6233.09,3798.5 D4.2@6252,3779.59 ; D4.2@6252,3779.59 D4.2@6254,3779.59 6256.59,3791 6297,3791 UC2.1@6297,3787 ; 6273.06,3791 UC2.1@6297,3787 ; UC2.1@6297,3787 6297,3789 6297,3782 6297,3782.5 6313,3798.5 ; UC2.1@6297,3787 6313,3798.5
  Bottom w5: R814.1@3105.29,2216.71 3112.02,2238.94 ; R814.1@3120.09,2217.16 3112.02,2238.94 ; 6230.59,3798.5 6151.86,3798.5 5138.86,2785.5 4191.47,2785.5 3862.47,2456.5 3329.58,2456.5 3112.02,2238.94 ; 6313,3798.5 6483.02,3798.5 USB1.3@6510,3771.52 ; 3112.02,2238.94 3112.02,2215.02 R814.1@3112.73,2215.73 3112.02,2238.94
UPHY0_PADP_1-CPU-RT0: R814.2 U1.C17 | length 611.3
  Top w5: U1.C17@2824.56,2140.9 2843.87,2131.13 ; U1.C17@2826.33,2143.67 U1.C17@2826.33,2143.81 ; U1.C17@2828.54,2146.4 2843.87,2131.13 ; v2@2915.97,2122.4 2891.83,2115 ; v2@2916.84,2111.5 2891.83,2115 ; U1.C17@2826.33,2143.81 2829.14,2141 2834,2141 ; U1.C17@2826.33,2143.81 2843.87,2131.13 ; U1.C17@2826.33,2143.81 2834,2141 ; U1.C17@2826.33,2143.81 2834,2141 ; 2834,2141 2860,2115 2915,2115 v2(2917,2117) 2891.83,2115 ; 2834,2141 2828.15,2146.69 2834,2141 ; 2834,2141 2825.85,2140.44 2834,2141
  Bottom w5: v2@2912.36,2119.96 2923.93,2133 ; v2@2922.33,2115.64 2923.93,2133 ; R814.2@3084.99,2197.42 3067.8,2188 ; R814.2@3086.7,2182.79 3067.8,2188 ; R814.2@3087.98,2190.98 R814.2@3087.27,2190.27 ; 2923.93,2133 3012.8,2133 3067.8,2188 ; 2923.93,2133 2917,2126.07 v2(2917,2117) 2923.93,2133 ; 3067.8,2188 3085,2188 R814.2@3087.27,2190.27 ; 3067.8,2188 R814.2@3087.27,2190.27
UPHY0_VRES_1-CPU-RT0: C69.2 R51.1 U1.C15 | length 232.1
  Top w4.5: v2(2790,2196.5) 2790.14,2196.36 v2@2790.14,2195.5
  Top w8: v2(2790,2196.5) U1.C15@2790.14,2180 v2@2790.14,2195.5
  Bottom w10: v2(2790,2196.5) 2846.5,2196.5 2850,2200 2849,2199 2850,2198 C69.2@2850,2168 ; 2808.46,2196.5 R51.1@2849,2200 ; R51.1@2849,2200 C69.2@2850,2168 ; R51.1@2849,2200 C69.2@2850,2168
V12_1-CPU-RT0: C48.1 R829.2 | length 135.2
  Top w20: C48.1@3199.55,2167 R829.2@3200,2105 3200,2177.55 C48.1@3199.55,2178
WAN_C1_4-ETHERNET: R122.1 U15.4 U15.5 | length 1172.1
  Top w20: U15.4@3597,664 R122.1@3597,734 ; R122.1@3597,734 3597,660 U15.4@3610,647 ; R122.1@3597,734 3592.46,646.15 R122.1@3597,734 ; R122.1@3597,734 3627.02,651.32 R122.1@3597,734 ; R122.1@3597,734 U15.4@3610,647 ; R122.1@3597,734 U15.4@3610,647
  Bottom w20: U15.4@3592.74,643.79 3610,599 ; U15.4@3627.26,643.79 3610,599 ; U15.5@3646.16,536.19 3609,598 ; U15.5@3670.81,560.84 3609,598 ; 3609,598 U15.5@3660,547 3609,598 ; 3609,598 3610,599 ; 3610,599 U15.4@3610,647 3610,599
WAN_C2_4-ETHERNET: R123.1 U15.7 U15.8 | length 1065.8
  Top w20: U15.7@3749.12,560.78 3813,600 ; U15.7@3760,547 3813,600 ; U15.7@3773.78,536.12 3813,600 ; U15.8@3792.99,642.63 3813,600 ; U15.8@3809,660 R123.1@3809,730 ; U15.8@3827.42,644.83 3813,600 ; R123.1@3809,730 3809,648 U15.8@3810,647 ; R123.1@3809,730 3792.52,648.65 R123.1@3809,730 ; R123.1@3809,730 3827.44,649.07 R123.1@3809,730 ; R123.1@3809,730 U15.8@3810,647 ; R123.1@3809,730 U15.8@3810,647 ; U15.8@3810,647 3813,644 3813,600 ; U15.8@3810,647 3813,600
WANLED_6-LED1: D12.1 R167.1 | length 343.8
  Top w4.5: D12.1@1547.06,3940.74 1558,3915.49 ; R167.1@1550.36,3889.28 1558,3911.5 ; D12.1@1551.38,3942.2 1558,3915.49 ; R167.1@1554.76,3888.22 1558,3911.5 ; D12.1@1555.84,3942.92 1558,3915.49 ; R167.1@1558,3888 1558,3944.41 D12.1@1558.59,3945 ; D12.1@1558.59,3943 1558,3915.49 ; R167.1@1561.24,3888.22 1558,3911.5 ; D12.1@1561.33,3942.8 1558,3915.49 ; R167.1@1565.64,3889.28 1558,3911.5 ; D12.1@1565.76,3941.89 1558,3915.49 ; D12.1@1570.01,3940.25 1558,3915.49
WDT_RST_N: R343.2 U1.D6 U4.3 | length 2302.4
  Top w4: R343.2@2960,3590 2961,3590 R343.2@2962.26,3588.74
  Top w4.5: R343.2@2952.42,3591.6 2961,3613.54 ; R343.2@2952.71,3587.36 2965,3564.82 ; U4.3@2953.63,3667.98 2961,3646.63 ; R343.2@2956.77,3590.36 2961,3613.54 ; R343.2@2956.86,3589.17 2965,3564.82 ; U4.3@2958.02,3669.02 2961,3646.63 ; U4.3@2962.63,3669.16 2961,3646.63 ; R343.2@2963.22,3590.43 2965,3564.82 ; R343.2@2963.25,3590.09 2961,3613.54 ; U4.3@2967.08,3668.38 2961,3646.63 ; R343.2@2967.69,3590.95 2961,3613.54 ; R343.2@2967.74,3590.34 2965,3564.82 ; v1@3026.87,3267.26 3011.45,3293.55 ; v1@3030.58,3269.83 3011.45,3293.55 ; v1@3035.17,3274.42 3011.45,3293.55 ; v1@3037.74,3278.13 3011.45,3293.55 ; 2961,3613.54 R343.2@2960,3590 2965,3564.82 ; 2961,3646.63 U4.3@2960.32,3669.2 2961,3669.2 2961,3590 2962.26,3588.74 2965,3586 2965,3340 v1(3033,3272) 3011.45,3293.55
  Top w8: U1.D6@2609.19,2324.76 2625.24,2324.76 U1.D6@2609.19,2324.76 ; U1.D6@2609.19,2324.76 v2(2625.5,2324.5) U1.D6@2609.19,2324.76
  Top w10: v2@2625.24,2324.76 v2(2625.5,2324.5)
  Inner Layer 3 w4.5: v2(2625.5,2324.5) 2662.19,2324.5 2673.69,2336 2706.44,2336 2746,2375.56 2746,2404.72 3010,2668.72 3010,3230.73 3033,3253.73 ; v2@2626.2,2318.79 2649,2324.5 v2@2626.2,2330.21 ; v1@3025.43,3270.36 3033,3253.73 ; v1@3029.76,3271.71 3033,3253.73 ; v1@3036.24,3271.71 3033,3253.73 ; v1@3040.57,3270.36 3033,3253.73 ; 3033,3253.73 v1(3033,3272) 3033,3253.73
WLAN_LED: C847.1 D6.2 R132.2 R134.2 U1.G4 | length 9764.7
  Top w4.5: D6.2@1725.99,3940.25 1738,3915.49 ; D6.2@1730.24,3941.89 1738,3915.49 ; D6.2@1734.67,3942.8 1738,3915.49 ; D6.2@1737.41,3943 1738,3915.49 ; D6.2@1737.41,3945 1738,3944.41 1738,3850 1603,3715 1603,3320 1913,3010 1913,2914 2062,2765 2093,2734 R132.2@2103,2734 ; D6.2@1740.16,3942.92 1738,3915.49 ; D6.2@1744.62,3942.2 1738,3915.49 ; D6.2@1748.94,3940.74 1738,3915.49 ; C847.1@2062.03,2763.05 2082.21,2744.79 ; C847.1@2063.01,2762.07 2043.23,2783.77 ; C847.1@2065.33,2766.14 2082.21,2744.79 ; C847.1@2066.11,2765.36 2043.23,2783.77 ; C847.1@2069.59,2770.83 2043.23,2783.77 ; C847.1@2070.87,2769.53 2082.21,2744.79 ; C847.1@2071.26,2775.03 2043.23,2783.77 ; C847.1@2075.12,2771.06 2082.21,2744.79 ; R132.2@2097.91,2727.15 2081.58,2746.5 ; R132.2@2098.08,2727.01 2080.03,2746.83 ; R132.2@2101.16,2730.32 2080.03,2746.83 ; R132.2@2101.13,2730.34 2081.15,2746.35 ; R132.2@2102,2735 2102,2735.25 2102.25,2735.25 R132.2@2104.5,2733 ; R132.2@2104.55,2735.85 2081.58,2746.5 ; R132.2@2104.62,2735.82 2080.62,2747.76 ; R132.2@2106.08,2740.11 2081.58,2746.5 ; R132.2@2106.29,2740.02 2080.62,2747.76 ; v1@2123.92,2703.19 R132.2@2108.32,2729.18 ; v1@2127.61,2705.8 R132.2@2108.32,2729.18 ; v1@2132.14,2710.44 R132.2@2108.32,2729.18 ; v1@2134.66,2714.19 R132.2@2108.32,2729.18 ; 2043.23,2783.77 C847.1@2068,2768 2082.21,2744.79 ; 2078.64,2748.36 R132.2@2098.02,2727.06 ; 2078.64,2748.36 R132.2@2106.21,2740.05 ; 2078.64,2748.36 R132.2@2101.11,2730.35 ; 2078.64,2748.36 R132.2@2104.58,2735.84 ; 2078.64,2748.36 R132.2@2103,2733 ; 2078.64,2748.36 R132.2@2098.02,2727.06 ; 2078.64,2748.36 R132.2@2106.21,2740.05 ; 2078.64,2748.36 R132.2@2101.11,2730.35 ; 2078.64,2748.36 R132.2@2104.58,2735.84 ; 2078.64,2748.36 R132.2@2103,2733 ; 2080.03,2746.83 2106,2740.15 2081.15,2746.35 ; 2080.03,2746.83 2104.5,2735.88 2081.15,2746.35 ; 2080.03,2746.83 R132.2@2103,2733 ; 2080.62,2747.76 2097.84,2727.21 2081.54,2746.96 ; 2080.62,2747.76 2101.05,2730.4 2081.54,2746.96 ; 2080.62,2747.76 R132.2@2103,2733 ; 2081.15,2746.35 R132.2@2098.01,2727.07 ; 2081.15,2746.35 R132.2@2103,2733 ; 2081.54,2746.96 R132.2@2106.19,2740.06 ; 2081.54,2746.96 R132.2@2104.6,2735.83 ; 2081.54,2746.96 R132.2@2103,2733 ; 2081.58,2746.5 R132.2@2101.09,2730.37 ; 2081.58,2746.5 R132.2@2103,2733 ; R132.2@2098.6,2726.62 v1@2123.03,2714.47 ; R132.2@2098.6,2726.62 v1@2123.03,2714.47 ; R132.2@2098.6,2726.62 v1@2123.03,2714.47 ; R132.2@2098.6,2726.62 v1@2123.03,2714.47 ; R132.2@2098.6,2726.62 v1@2123.03,2714.47 ; R132.2@2098.6,2726.62 v1@2123.03,2714.47 ; R132.2@2098.6,2726.62 v1@2122.91,2714.58 ; R132.2@2100.94,2730.49 v1@2123.03,2714.47 ; R132.2@2100.94,2730.49 v1@2123.03,2714.47 ; R132.2@2100.94,2730.49 v1@2123.03,2714.47 ; R132.2@2100.94,2730.49 v1@2123.03,2714.47 ; R132.2@2100.94,2730.49 v1@2123.03,2714.47 ; R132.2@2100.94,2730.49 v1@2123.03,2714.47 ; R132.2@2100.94,2730.49 v1@2122.91,2714.58 ; R132.2@2103,2733 R132.2@2104.5,2733 ; R132.2@2103,2733 v1@2123.03,2714.47 ; R132.2@2103,2733 v1@2123.03,2714.47 ; R132.2@2103,2733 v1@2123.03,2714.47 ; R132.2@2103,2733 v1@2123.03,2714.47 ; R132.2@2103,2733 v1@2123.03,2714.47 ; R132.2@2103,2733 v1@2123.03,2714.47 ; R132.2@2104.5,2733 2129.75,2707.75 v1(2130,2708) ; R132.2@2105.35,2735.25 v1@2123.03,2714.47 ; R132.2@2105.35,2735.25 v1@2123.03,2714.47 ; R132.2@2105.35,2735.25 v1@2123.03,2714.47 ; R132.2@2105.35,2735.25 v1@2123.03,2714.47 ; R132.2@2105.35,2735.25 v1@2123.03,2714.47 ; R132.2@2105.35,2735.25 v1@2123.03,2714.47 ; R132.2@2105.35,2735.25 v1@2122.91,2714.58 ; 2106.4,2722.74 v1@2125.02,2702.06 ; 2106.4,2722.74 v1@2133.15,2715.08 ; 2106.4,2722.74 v1@2128.12,2705.35 ; 2106.4,2722.74 v1@2131.56,2710.85 ; 2106.4,2722.74 v1(2130,2708) ; 2106.4,2722.74 v1@2125.02,2702.06 ; 2106.4,2722.74 v1@2133.15,2715.08 ; 2106.4,2722.74 v1@2128.12,2705.35 ; 2106.4,2722.74 v1@2131.56,2710.85 ; 2106.4,2722.74 v1(2130,2708) ; 2106.4,2722.74 v1@2125.02,2702.06 ; 2106.4,2722.74 v1@2133.15,2715.08 ; 2106.4,2722.74 v1@2128.12,2705.35 ; 2106.4,2722.74 v1@2131.56,2710.85 ; 2106.4,2722.74 v1(2130,2708) ; 2106.4,2722.74 v1@2125.02,2702.06 ; 2106.4,2722.74 v1@2133.15,2715.08 ; 2106.4,2722.74 v1@2128.12,2705.35 ; 2106.4,2722.74 v1@2131.56,2710.85 ; 2106.4,2722.74 v1(2130,2708) ; 2106.4,2722.74 v1@2125.02,2702.06 ; 2106.4,2722.74 v1@2133.15,2715.08 ; 2106.4,2722.74 v1@2128.12,2705.35 ; 2106.4,2722.74 v1@2131.56,2710.85 ; 2106.4,2722.74 v1(2130,2708) ; 2106.4,2722.74 v1@2125.02,2702.06 ; 2106.4,2722.74 v1@2133.15,2715.08 ; 2106.4,2722.74 v1@2128.12,2705.35 ; 2106.4,2722.74 v1@2131.56,2710.85 ; 2106.4,2722.74 v1(2130,2708) ; 2106.39,2722.76 v1@2125.02,2702.06 ; 2106.39,2722.76 v1@2133.15,2715.08 ; 2106.39,2722.76 v1@2128.12,2705.35 ; 2106.39,2722.76 v1@2131.56,2710.85 ; 2106.39,2722.76 v1(2130,2708) ; R132.2@2107.43,2725.78 v1@2124.43,2702.61 ; R132.2@2107.43,2725.78 v1@2133.93,2714.68 ; R132.2@2107.43,2725.78 v1@2127.85,2705.56 ; R132.2@2107.43,2725.78 v1@2131.86,2710.66 ; R132.2@2107.43,2725.78 v1(2130,2708) ; R132.2@2107.43,2725.78 v1@2124.43,2702.61 ; R132.2@2107.43,2725.78 v1@2133.93,2714.68 ; R132.2@2107.43,2725.78 v1@2127.85,2705.56 ; R132.2@2107.43,2725.78 v1@2131.86,2710.66 ; R132.2@2107.43,2725.78 v1(2130,2708) ; R132.2@2107.43,2725.78 v1@2124.43,2702.61 ; R132.2@2107.43,2725.78 v1@2133.93,2714.68 ; R132.2@2107.43,2725.78 v1@2127.85,2705.56 ; R132.2@2107.43,2725.78 v1@2131.86,2710.66 ; R132.2@2107.43,2725.78 v1(2130,2708) ; R132.2@2107.43,2725.78 v1@2124.43,2702.61 ; R132.2@2107.43,2725.78 v1@2133.93,2714.68 ; R132.2@2107.43,2725.78 v1@2127.85,2705.56 ; R132.2@2107.43,2725.78 v1@2131.86,2710.66 ; R132.2@2107.43,2725.78 v1(2130,2708) ; R132.2@2107.43,2725.78 v1@2124.43,2702.61 ; R132.2@2107.43,2725.78 v1@2133.93,2714.68 ; R132.2@2107.43,2725.78 v1@2127.85,2705.56 ; R132.2@2107.43,2725.78 v1@2131.86,2710.66 ; R132.2@2107.43,2725.78 v1(2130,2708) ; R132.2@2107.43,2725.78 v1@2124.43,2702.61 ; R132.2@2107.43,2725.78 v1@2133.93,2714.68 ; R132.2@2107.43,2725.78 v1@2127.85,2705.56 ; R132.2@2107.43,2725.78 v1@2131.86,2710.66 ; R132.2@2107.43,2725.78 v1(2130,2708) ; R132.2@2107.43,2725.78 v1@2124.43,2702.62 ; R132.2@2107.43,2725.78 v1@2133.93,2714.68 ; R132.2@2107.43,2725.78 v1@2127.85,2705.57 ; R132.2@2107.43,2725.78 v1@2131.86,2710.66 ; R132.2@2107.43,2725.78 v1(2130,2708) ; R132.2@2108.1,2728.29 v1@2124.04,2703.05 ; R132.2@2108.1,2728.29 v1@2134.48,2714.32 ; R132.2@2108.1,2728.29 v1@2127.67,2705.74 ; R132.2@2108.1,2728.29 v1@2132.08,2710.5 ; R132.2@2108.1,2728.29 v1(2130,2708) ; R132.2@2108.1,2728.29 v1@2124.04,2703.05 ; R132.2@2108.1,2728.29 v1@2134.48,2714.32 ; R132.2@2108.1,2728.29 v1@2127.67,2705.74 ; R132.2@2108.1,2728.29 v1@2132.08,2710.5 ; R132.2@2108.1,2728.29 v1(2130,2708) ; R132.2@2108.1,2728.29 v1@2124.04,2703.05 ; R132.2@2108.1,2728.29 v1@2134.48,2714.32 ; R132.2@2108.1,2728.29 v1@2127.67,2705.74 ; R132.2@2108.1,2728.29 v1@2132.08,2710.5 ; R132.2@2108.1,2728.29 v1(2130,2708) ; R132.2@2108.1,2728.29 v1@2124.04,2703.05 ; R132.2@2108.1,2728.29 v1@2134.48,2714.32 ; R132.2@2108.1,2728.29 v1@2127.67,2705.74 ; R132.2@2108.1,2728.29 v1@2132.08,2710.5 ; R132.2@2108.1,2728.29 v1(2130,2708) ; R132.2@2108.1,2728.29 v1@2124.04,2703.05 ; R132.2@2108.1,2728.29 v1@2134.48,2714.32 ; R132.2@2108.1,2728.29 v1@2127.67,2705.74 ; R132.2@2108.1,2728.29 v1@2132.08,2710.5 ; R132.2@2108.1,2728.29 v1(2130,2708) ; R132.2@2108.1,2728.29 v1@2124.04,2703.05 ; R132.2@2108.1,2728.29 v1@2134.48,2714.32 ; R132.2@2108.1,2728.29 v1@2127.67,2705.74 ; R132.2@2108.1,2728.29 v1@2132.08,2710.5 ; R132.2@2108.1,2728.29 v1(2130,2708) ; R132.2@2108.32,2729.18 v1(2130,2708) ; R132.2@2109.02,2737.88 v1@2123.03,2714.47 ; R132.2@2109.02,2737.88 v1@2123.03,2714.47 ; R132.2@2109.02,2737.88 v1@2123.03,2714.47 ; R132.2@2109.02,2737.88 v1@2123.03,2714.47 ; R132.2@2109.02,2737.88 v1@2123.03,2714.47 ; R132.2@2109.02,2737.88 v1@2123.03,2714.47 ; R132.2@2109.02,2737.88 v1@2122.91,2714.58 ; R132.2@2109.9,2729.9 v1@2123.66,2703.55 ; R132.2@2109.9,2729.9 v1@2134.98,2713.94 ; R132.2@2109.9,2729.9 v1@2127.49,2705.94 ; R132.2@2109.9,2729.9 v1@2132.27,2710.33 ; R132.2@2109.9,2729.9 v1(2130,2708) ; R132.2@2109.9,2729.9 v1@2123.66,2703.55 ; R132.2@2109.9,2729.9 v1@2134.98,2713.94 ; R132.2@2109.9,2729.9 v1@2127.49,2705.94 ; R132.2@2109.9,2729.9 v1@2132.27,2710.33 ; R132.2@2109.9,2729.9 v1(2130,2708) ; R132.2@2109.9,2729.9 v1@2123.66,2703.55 ; R132.2@2109.9,2729.9 v1@2134.98,2713.94 ; R132.2@2109.9,2729.9 v1@2127.49,2705.94 ; R132.2@2109.9,2729.9 v1@2132.27,2710.33 ; R132.2@2109.9,2729.9 v1(2130,2708) ; R132.2@2109.9,2729.9 v1@2123.66,2703.55 ; R132.2@2109.9,2729.9 v1@2134.98,2713.94 ; R132.2@2109.9,2729.9 v1@2127.49,2705.94 ; R132.2@2109.9,2729.9 v1@2132.27,2710.33 ; R132.2@2109.9,2729.9 v1(2130,2708) ; R132.2@2109.9,2729.9 v1@2123.66,2703.55 ; R132.2@2109.9,2729.9 v1@2134.98,2713.94 ; R132.2@2109.9,2729.9 v1@2127.49,2705.94 ; R132.2@2109.9,2729.9 v1@2132.27,2710.33 ; R132.2@2109.9,2729.9 v1(2130,2708) ; R132.2@2109.9,2729.9 v1@2123.66,2703.55 ; R132.2@2109.9,2729.9 v1@2134.98,2713.94 ; R132.2@2109.9,2729.9 v1@2127.49,2705.94 ; R132.2@2109.9,2729.9 v1@2132.27,2710.33 ; R132.2@2109.9,2729.9 v1(2130,2708) ; R132.2@2109.89,2729.9 v1@2123.66,2703.55 ; R132.2@2109.89,2729.9 v1@2134.98,2713.94 ; R132.2@2109.89,2729.9 v1@2127.49,2705.94 ; R132.2@2109.89,2729.9 v1@2132.27,2710.33 ; R132.2@2109.89,2729.9 v1(2130,2708) ; 2113.16,2730.96 v1@2123.18,2704.31 ; 2113.16,2730.96 v1@2135.57,2713.39 ; 2113.16,2730.96 v1@2127.27,2706.23 ; 2113.16,2730.96 v1@2132.51,2710.07 ; 2113.16,2730.96 v1(2130,2708) ; 2113.16,2730.96 v1@2123.18,2704.31 ; 2113.16,2730.96 v1@2135.57,2713.39 ; 2113.16,2730.96 v1@2127.27,2706.23 ; 2113.16,2730.96 v1@2132.51,2710.07 ; 2113.16,2730.96 v1(2130,2708) ; 2113.16,2730.96 v1@2123.18,2704.31 ; 2113.16,2730.96 v1@2135.57,2713.39 ; 2113.16,2730.96 v1@2127.27,2706.23 ; 2113.16,2730.96 v1@2132.51,2710.07 ; 2113.16,2730.96 v1(2130,2708) ; 2113.16,2730.96 v1@2123.18,2704.31 ; 2113.16,2730.96 v1@2135.57,2713.39 ; 2113.16,2730.96 v1@2127.27,2706.23 ; 2113.16,2730.96 v1@2132.51,2710.07 ; 2113.16,2730.96 v1(2130,2708) ; 2113.16,2730.96 v1@2123.18,2704.31 ; 2113.16,2730.96 v1@2135.57,2713.39 ; 2113.16,2730.96 v1@2127.27,2706.23 ; 2113.16,2730.96 v1@2132.51,2710.07 ; 2113.16,2730.96 v1(2130,2708) ; 2113.16,2730.96 v1@2123.18,2704.31 ; 2113.16,2730.96 v1@2135.57,2713.39 ; 2113.16,2730.96 v1@2127.27,2706.23 ; 2113.16,2730.96 v1@2132.51,2710.07 ; 2113.16,2730.96 v1(2130,2708) ; 2113.14,2730.97 v1@2123.19,2704.31 ; 2113.14,2730.97 v1@2135.57,2713.39 ; 2113.14,2730.97 v1@2127.27,2706.23 ; 2113.14,2730.97 v1@2132.51,2710.07 ; 2113.14,2730.97 v1(2130,2708)
  Top w5: C847.1@2062,2765 2066.5,2769.5 2066.5,2768 C847.1@2068,2768 ; R132.2@2102,2735 2103,2734 R132.2@2103,2733
  Top w8: v2(2518.7,2289.2) U1.G4@2518.71,2306.67 v2(2518.7,2289.2)
  Inner Layer 3 w4.5: v1@2122.34,2706.82 2130,2682.5 ; v1@2126.76,2707.79 2130,2682.5 ; v1@2133.24,2707.79 2130,2682.5 ; v1@2137.66,2706.82 2130,2682.5 ; v2@2513.87,2286.08 2501.11,2311.16 ; v2@2522.8,2293.23 2501.11,2311.16 ; 2130,2682.5 v1(2130,2708) 2130,2682.27 2518.7,2293.57 v2(2518.7,2289.2) 2501.11,2311.16
WLED_5G_6-LED1: D17.1 R156.1 | length 309.7
  Bottom w4: D17.1@3977.32,3338.36 3989,3361.59 ; D17.1@3981.1,3336.82 3989,3361.59 ; R156.1@3982.08,3376.91 3989,3355.97 ; D17.1@3985.01,3335.9 3989,3361.59 ; R156.1@3986,3377.82 3989,3355.97 ; D17.1@3989,3335.59 3989,3378 R156.1@3990,3378 3989,3355.97 ; D17.1@3992.99,3335.9 3989,3361.59 ; R156.1@3993.96,3377.46 3989,3355.97 ; D17.1@3996.9,3336.82 3989,3361.59 ; R156.1@3997.79,3376.19 3989,3355.97 ; D17.1@4000.68,3338.36 3989,3361.59
WLED_6-LED1: D6.1 R155.1 | length 343.8
  Top w4.5: D6.1@1777.06,3940.74 1788,3915.49 ; R155.1@1780.36,3889.28 1788,3911.5 ; D6.1@1781.38,3942.2 1788,3915.49 ; R155.1@1784.76,3888.22 1788,3911.5 ; D6.1@1785.84,3942.92 1788,3915.49 ; R155.1@1788,3888 1788,3944.41 D6.1@1788.59,3945 ; D6.1@1788.59,3943 1788,3915.49 ; R155.1@1791.24,3888.22 1788,3911.5 ; D6.1@1791.33,3942.8 1788,3915.49 ; R155.1@1795.64,3889.28 1788,3911.5 ; D6.1@1795.76,3941.89 1788,3915.49 ; D6.1@1800.01,3940.25 1788,3915.49
WP_2-MEMORY: SR2.2 U18.3 | length 324.3
  Top w4: U18.3@3225,3710.2 U18.3@3225,3717
  Top w4.5: U18.3@3214.11,3696.67 3225,3672.09 ; U18.3@3218.41,3698.16 3225,3672.09 ; SR2.2@3219.27,3655.62 3225,3678.65 ; SR2.2@3223.75,3654.95 3225,3678.65 ; U18.3@3225,3698.98 3225,3672.09 ; U18.3@3225,3717 3225,3656 3227,3656 SR2.2@3228,3655 ; SR2.2@3227,3655 3225,3678.65 ; SR2.2@3230.21,3655.49 3225,3678.65 ; U18.3@3231.59,3698.16 3225,3672.09 ; SR2.2@3234.51,3656.9 3225,3678.65 ; U18.3@3235.89,3696.67 3225,3672.09
WPS_PBC: R154.2 R808.1 S2.1 | length 1056.5
  Top w4.5: S2.1@110,3458.58 138,3430.58 306.06,3430.58 R154.2@309.44,3427.2 ; R808.1@290.36,3104.28 298,3126.5 ; R808.1@294.76,3103.22 298,3126.5 ; R808.1@298,3103 298,3415.76 ; R808.1@301.24,3103.22 298,3126.5 ; R154.2@301.94,3429.16 298,3398.77 ; R808.1@305.64,3104.28 298,3126.5 ; R154.2@306.36,3428.25 298,3398.77 ; R154.2@307.17,3419.79 285.21,3430.58 ; R154.2@308.78,3424.02 285.21,3430.58 ; R154.2@309.28,3434.95 285.21,3430.58 ; R154.2@309.67,3430.44 285.21,3430.58 ; R154.2@312.39,3425.83 298,3398.77 ; R154.2@316.21,3423.42 298,3398.77 ; 285.21,3430.58 R154.2@309.44,3427.2 ; 298,3398.77 R154.2@309.44,3427.2 ; 298,3415.76 R154.2@309.44,3427.2 ; 298,3415.76 313.45,3420.57 298,3415.76 ; 298,3415.76 302.81,3431.21 298,3415.76 ; 298,3415.76 311.5,3424.68 298,3415.76 ; 298,3415.76 306.92,3429.26 298,3415.76 ; 298,3415.76 R154.2@309.44,3427.2
WPSLED+_6-LED1: D26.1 R374.1 | length 243.3
  Top w5: D26.1@2793.19,4045.49 2805,4019 ; R374.1@2797.58,4004.12 2805,4028 R374.1@2812.42,4004.12 ; D26.1@2797.97,4047.14 2805,4019 ; D26.1@2804.41,4048 2805,4019 ; D26.1@2804.41,4050 2805,4049.41 R374.1@2805,4003 R374.1@2805,4002 ; D26.1@2810.88,4047.4 2805,4019 ; D26.1@2815.73,4045.95 2805,4019
X1_IP1001-2_1-CPU-RT0: C803.1 R747.2 U609.33 X602.1 | length 1386.1
  Top w5: U609.33@5852.63,2429.22 5852.63,2438 5858.63,2444 ; U609.33@5852.63,2436.11 5858.63,2444 ; R747.2@6043.66,2468 6038,2484 ; R747.2@6044.06,2476.58 6029.39,2451.39 ; R747.2@6054,2478.34 6038,2484 ; R747.2@6054.58,2466.06 6029.39,2451.39 ; X602.1@6127.04,2594.19 6093.84,2615.05 ; X602.1@6127.04,2635.91 6093.84,2615.05 ; X602.1@6129.49,2598.72 6093.84,2615.05 ; X602.1@6129.49,2631.38 6093.84,2615.05 ; X602.1@6131.3,2603.47 6093.84,2615.05 ; X602.1@6131.3,2626.63 6093.84,2615.05 ; X602.1@6132.48,2608.36 6093.84,2615.05 ; X602.1@6132.48,2621.74 6093.84,2615.05 ; 5858.63,2444 6022,2444 R747.2@6050,2472 ; 6029.39,2451.39 R747.2@6050,2472 ; 6038,2484 6038,2602 6051.05,2615.05 X602.1@6133.05,2615.05 6093.84,2615.05 ; 6038,2484 R747.2@6050,2472
  Bottom w5: X602.1@6133.05,2615.05 6189.05,2615.05 C803.1@6190,2616 6164.97,2615.05 ; X602.1@6133.63,2608.36 6172.27,2615.05 ; X602.1@6133.63,2621.74 6172.27,2615.05 ; X602.1@6134.8,2603.47 6172.27,2615.05 ; X602.1@6134.8,2626.63 6172.27,2615.05 ; X602.1@6136.61,2598.72 6172.27,2615.05 ; X602.1@6136.61,2631.38 6172.27,2615.05 ; X602.1@6139.06,2594.19 6172.27,2615.05 ; X602.1@6139.06,2635.91 6172.27,2615.05 ; C803.1@6188.6,2623.37 6164.97,2615.05 ; C803.1@6189.16,2608.55 6164.97,2615.05
X1_IP1001-CO_1-CPU-RT0: R745.2 R746.2 | length 956.8
  Top w5: R746.2@5106.83,2752.45 5131.05,2746 ; R746.2@5107.42,2737.64 5131.05,2746 ; R745.2@5903.83,2757.18 5879.82,2746 ; R745.2@5906.07,2742.5 5879.82,2746 ; 5131.05,2746 R746.2@5106,2745 5107,2746 5902,2746 R745.2@5906,2750 5879.82,2746
X1_IP1001_1-CPU-RT0: C801.1 R734.2 R833.2 U607.33 X601.1 | length 3657.6
  Top w4.5: R734.2@4779,2036.5 4780,2035.5 R734.2@4780,2029
  Top w5: 4606.97,2023 U607.33@4578.63,2011.22 4578.63,2021 4580.63,2023 4649,2023 4664,2008 4758,2008 4779,2029 4779,2036.5 4863.56,2036.5 4943.99,2116.93 4943.99,2147.05 4963.99,2167.05 X601.1@5039.05,2167.05 ; R734.2@4774.17,2033.71 4759.12,2009.12 ; R734.2@4778.97,2036.43 4806.83,2036.5 ; R734.2@4782.97,2022.11 4806.83,2036.5 ; R734.2@4784.42,2022.94 4759.12,2009.12 ; X601.1@5017.78,2171.38 5036,2206.46 ; X601.1@5022.49,2169.31 5036,2206.46 ; X601.1@5027.37,2167.89 5036,2206.46 ; R833.2@5028.58,2673.88 5036,2650 ; X601.1@5032.34,2167.1 5036,2206.46 ; X601.1@5033.04,2146.19 4999.84,2167.05 ; X601.1@5033.04,2187.91 4999.84,2167.05 ; X601.1@5035.49,2150.72 4999.84,2167.05 ; X601.1@5035.49,2183.38 4999.84,2167.05 ; X601.1@5037.3,2155.47 4999.84,2167.05 ; X601.1@5037.3,2178.63 4999.84,2167.05 ; X601.1@5038.48,2160.36 4999.84,2167.05 ; X601.1@5038.48,2173.74 4999.84,2167.05 ; R833.2@5043.42,2673.88 5036,2650 ; X601.1@5045.68,2168.13 5036,2206.46 ; X601.1@5050.47,2169.67 5036,2206.46 ; X601.1@5055.07,2171.83 5036,2206.46 ; X601.1@5059.41,2174.61 5036,2206.46 ; 4759.12,2009.12 R734.2@4780,2029 4806.83,2036.5 ; 5036,2206.46 X601.1@5039.05,2167.05 ; 5036,2650 R833.2@5036,2675 5036,2170.1 X601.1@5039.05,2167.05
  Bottom w5: X601.1@5038.58,2173.75 C801.1@5082.12,2173.43 ; X601.1@5038.83,2160.34 C801.1@5081.58,2162.3 ; X601.1@5038.91,2178.76 C801.1@5082.12,2173.43 ; X601.1@5039.36,2155.34 C801.1@5081.58,2162.3 ; X601.1@5039.51,2173.75 C801.1@5079.82,2167.63 ; X601.1@5039.62,2160.36 5078.27,2167 ; X601.1@5039.64,2173.74 5078.27,2167 ; X601.1@5039.7,2160.37 C801.1@5079.82,2167.63 ; X601.1@5039.82,2183.74 C801.1@5082.12,2173.43 ; X601.1@5040.32,2173.64 C801.1@5081.58,2162.3 ; X601.1@5040.48,2150.4 C801.1@5081.58,2162.3 ; X601.1@5040.55,2160.51 C801.1@5082.12,2173.43 ; X601.1@5040.57,2178.66 C801.1@5079.82,2167.63 ; X601.1@5040.79,2155.47 5078.27,2167 ; X601.1@5040.82,2178.63 5078.27,2167 ; X601.1@5040.9,2155.48 C801.1@5079.82,2167.63 ; X601.1@5041.33,2188.64 C801.1@5082.12,2173.43 ; X601.1@5041.93,2178.4 C801.1@5081.58,2162.3 ; X601.1@5042.2,2145.57 C801.1@5081.58,2162.3 ; X601.1@5042.24,2183.46 C801.1@5079.82,2167.63 ; X601.1@5042.31,2155.8 C801.1@5082.12,2173.43 ; X601.1@5042.59,2150.72 5078.27,2167 ; X601.1@5042.64,2183.37 5078.27,2167 ; X601.1@5042.71,2150.74 C801.1@5079.82,2167.63 ; X601.1@5044.11,2182.98 C801.1@5081.58,2162.3 ; X601.1@5044.53,2188.06 C801.1@5079.82,2167.63 ; X601.1@5044.63,2151.3 C801.1@5082.12,2173.43 ; X601.1@5045.04,2146.18 5078.27,2167 ; X601.1@5045.09,2187.91 5078.27,2167 ; X601.1@5045.13,2146.21 C801.1@5079.82,2167.63 ; X601.1@5046.86,2187.31 C801.1@5081.58,2162.3 ; X601.1@5047.49,2147.04 C801.1@5082.12,2173.43 ; C801.1@5087.58,2175.36 5063.97,2167 ; C801.1@5088.17,2160.55 5063.97,2167 ; C801.1@5089,2167 5035.05,2167 5035,2167.05 X601.1@5039.05,2167.05 ; C801.1@5089,2168 5063.97,2167 ; X601.1@5039.05,2167.05 5078.27,2167 ; X601.1@5039.05,2167.05 C801.1@5081.58,2162.3 ; X601.1@5039.05,2167.05 C801.1@5082.12,2173.43 ; X601.1@5039.05,2167.05 C801.1@5079.82,2167.63
X1_IP1001_S_1-CPU-RT0: R746.1 R832.1 R833.1 | length 632.4
  Top w5: R832.1@5028.51,2745.42 R833.1@5030.82,2719.32 ; R833.1@5028.58,2712.12 5036,2736 R833.1@5043.42,2712.12 ; R832.1@5028.58,2743.88 R833.1@5036,2720 ; R832.1@5028.94,2742.48 R833.1@5041.18,2719.32 ; R833.1@5036,2711 R832.1@5036,2745 ; R832.1@5037.12,2737.58 5061,2745 R832.1@5037.12,2752.42 ; R832.1@5043.06,2742.48 R833.1@5030.82,2719.32 ; R832.1@5043.42,2743.88 R833.1@5036,2720 ; R832.1@5043.49,2745.42 R833.1@5041.18,2719.32 ; R746.1@5067.48,2737.94 R832.1@5044.32,2750.18 ; R746.1@5067.48,2752.06 R832.1@5044.32,2739.82 ; R746.1@5068.88,2737.58 R832.1@5045,2745 ; R746.1@5068.88,2752.42 R832.1@5045,2745 ; R746.1@5070.42,2737.51 R832.1@5044.32,2739.82 ; R746.1@5070.42,2752.49 R832.1@5044.32,2750.18 ; R833.1@5030.82,2719.32 R832.1@5036,2745 ; R833.1@5036,2720 R832.1@5036,2745 ; R832.1@5036,2745 R746.1@5070,2745 ; R832.1@5036,2745 R833.1@5041.18,2719.32 ; R832.1@5044.32,2739.82 R746.1@5070,2745 ; R832.1@5044.32,2750.18 R746.1@5070,2745 ; R832.1@5045,2745 R746.1@5070,2745
X2_IP1001-2_1-CPU-RT0: R748.2 U609.34 | length 193.7
  Top w5: U609.34@5832.94,2425.28 U609.34@5832.94,2436.11 ; R748.2@5936.94,2475.36 5926.06,2454 ; R748.2@5943.01,2470.95 5926.06,2454 ; R748.2@5947.42,2464.88 5926.06,2454 ; U609.34@5832.94,2436.11 5840,2443.16 ; U609.34@5832.94,2436.11 5840,2443.16 ; 5840,2443.16 5840,2443.93 5850.07,2454 5926.06,2454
